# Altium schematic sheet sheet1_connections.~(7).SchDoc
size A3; SheetNumber: 1; SheetTotal: 3
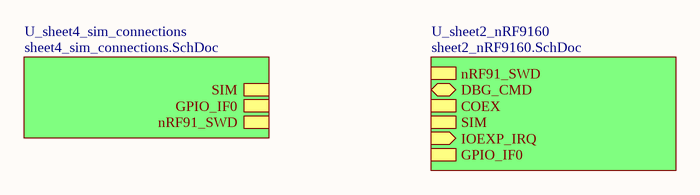
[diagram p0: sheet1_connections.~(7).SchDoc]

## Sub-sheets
U_sheet2_nRF9160 = sheet2_nRF9160.SchDoc: nRF91_SWD (harness SWD), DBG_CMD (bidir), COEX (harness COEX), SIM (harness SIM), IOEXP_IRQ (in), GPIO_IF0 (harness GPIO_IF0)
U_sheet4_sim_connections = sheet4_sim_connections.SchDoc: nRF91_SWD (harness SWD), GPIO_IF0 (harness GPIO_IF0), SIM (harness SIM)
